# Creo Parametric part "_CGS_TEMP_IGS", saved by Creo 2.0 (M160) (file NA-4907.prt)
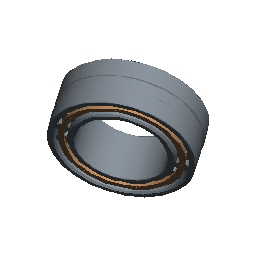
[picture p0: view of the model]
Units: Inch lbm Second (Pro/E Default); INCH, POUND, SECS

Created from: INLBS_PART_SOLID.PRT

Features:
  1. datum plane "RIGHT"
  2. datum plane "TOP"
  3. datum plane "FRONT"
  4. coordinate system
  5. imported feature "Import Feature id 40"
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
Layers: COLOR10, COLOR32, DWX_INNER_RACE_MM, DWX_LEFT_RETAINER_MM, DWX_OUTER_RACE_MM, DWX_RIGHT_RETAINER_MM, DWX_ROLLER_MM, DWX_ROLLER_MM_1, DWX_ROLLER_MM_10, DWX_ROLLER_MM_11, DWX_ROLLER_MM_12, DWX_ROLLER_MM_13, DWX_ROLLER_MM_14, DWX_ROLLER_MM_15, DWX_ROLLER_MM_16, DWX_ROLLER_MM_17, DWX_ROLLER_MM_18, DWX_ROLLER_MM_19, DWX_ROLLER_MM_2, DWX_ROLLER_MM_20, DWX_ROLLER_MM_3, DWX_ROLLER_MM_4, DWX_ROLLER_MM_5, DWX_ROLLER_MM_6, DWX_ROLLER_MM_7, DWX_ROLLER_MM_8, DWX_ROLLER_MM_9, ___SHELL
